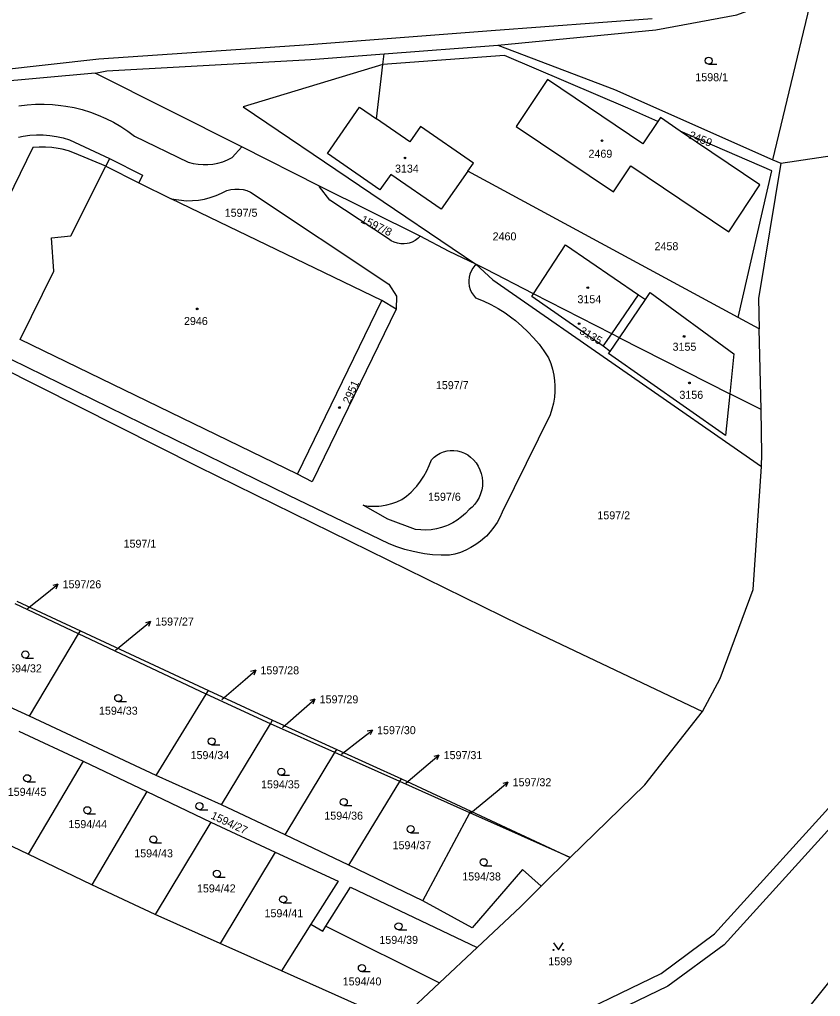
# Model space of a CAD drawing. Extents: x -679220 to -673243, y -1075091 to -1066557.
# Drawn here: x -677540.5 to -677370.2, y -1071612.6 to -1071405.1 of the extents above; entities that cross this region are included whole.
import ezdxf

# ---------------------------------------------------------------- set-up
doc = ezdxf.new("R2010")
doc.units = 0
for name, color, linetype in [('Hranice parcel', 7, 'Continuous'), ('Parcelní čísla', 7, 'Continuous'), ('Pop  PČ popisy', 7, 'Continuous'), ('Vnitřní kresba', 7, 'Continuous'), ('Značky budov', 7, 'Continuous'), ('Značky kultur', 7, 'Continuous')]:
    doc.layers.add(name, color=color, linetype=linetype)

msp = doc.modelspace()

# ---------------------------------------------------------------- linework, layer by layer
at = {"layer": 'Hranice parcel'}
for p, q in [((-677380.32, -1071434.86), (-677371.5, -1071397.98)), ((-677462.95, -1071412.35), (-677438.76, -1071410.53)), ((-677463.21, -1071414.59), (-677462.95, -1071412.35)), ((-677464.55, -1071426.16), (-677463.21, -1071414.59)), ((-677493.17, -1071432.13), (-677524.38, -1071416.45)), ((-677529.81, -1071430.6), (-677521.35, -1071434.58)), ((-677516, -1071429.8), (-677504.61, -1071435.33)), ((-677495.29, -1071434.36), (-677493.17, -1071432.13)), ((-677476.71, -1071440.48), (-677493.17, -1071432.13)), ((-677522.14, -1071436.19), (-677528.8, -1071433.41)), ((-677521.35, -1071434.58), (-677522.14, -1071436.19)), ((-677380.32, -1071434.86), (-677378.65, -1071435.6)), ((-677387.71, -1071468.34), (-677445.17, -1071437.26)), ((-677455.28, -1071451.1), (-677476.71, -1071440.48)), ((-677508.19, -1071443.16), (-677504.96, -1071443.55)), ((-677463.47, -1071464.77), (-677508.19, -1071443.16)), ((-677443.5, -1071457.04), (-677444.1, -1071457.88)), ((-677481.39, -1071501.64), (-677463.47, -1071464.77)), ((-677460.42, -1071466.58), (-677463.47, -1071464.77)), ((-677412.94, -1071472.64), (-677407.43, -1071464.52)), ((-677383.25, -1071470.75), (-677387.71, -1071468.34)), ((-677382.84, -1071487.91), (-677383.25, -1071470.75)), ((-677414.92, -1071475.56), (-677412.94, -1071472.64)), ((-677412.94, -1071472.64), (-677389.5, -1071484.56)), ((-677382.84, -1071487.91), (-677389.5, -1071484.56)), ((-677427.67, -1071489.01), (-677437.86, -1071509.71)), ((-677527.92, -1071535.57), (-677541.41, -1071529.19)), ((-677541.06, -1071528.61), (-677527.52, -1071534.91)), ((-677538.35, -1071553.02), (-677527.92, -1071535.57)), ((-677527.92, -1071535.57), (-677527.52, -1071534.91)), ((-677500.8, -1071548.41), (-677527.92, -1071535.57)), ((-677527.52, -1071534.91), (-677500.29, -1071547.58)), ((-677538.35, -1071553.02), (-677552.08, -1071546.78)), ((-677511.44, -1071565.66), (-677500.8, -1071548.41)), ((-677500.8, -1071548.41), (-677500.29, -1071547.58)), ((-677487.14, -1071554.68), (-677500.8, -1071548.41)), ((-677500.29, -1071547.58), (-677486.66, -1071553.87)), ((-677511.44, -1071565.66), (-677538.35, -1071553.02)), ((-677497.52, -1071571.92), (-677487.14, -1071554.68)), ((-677487.14, -1071554.68), (-677486.66, -1071553.87)), ((-677473.41, -1071560.79), (-677487.14, -1071554.68)), ((-677486.66, -1071553.87), (-677473.03, -1071560.16)), ((-677540.61, -1071556.25), (-677526.95, -1071562.58)), ((-677483.98, -1071578.29), (-677473.41, -1071560.79)), ((-677473.41, -1071560.79), (-677473.03, -1071560.16)), ((-677459.62, -1071566.94), (-677473.41, -1071560.79)), ((-677473.03, -1071560.16), (-677459.29, -1071566.4)), ((-677526.95, -1071562.58), (-677538.62, -1071582.4)), ((-677526.95, -1071562.58), (-677513.43, -1071569.04)), ((-677497.52, -1071571.92), (-677511.44, -1071565.66)), ((-677470.46, -1071584.7), (-677459.62, -1071566.94)), ((-677459.62, -1071566.94), (-677459.29, -1071566.4)), ((-677444.72, -1071573.58), (-677459.62, -1071566.94)), ((-677459.29, -1071566.4), (-677444.53, -1071573.23)), ((-677513.43, -1071569.04), (-677525.11, -1071588.88)), ((-677513.43, -1071569.04), (-677499.77, -1071575.57)), ((-677483.98, -1071578.29), (-677497.52, -1071571.92)), ((-677454.76, -1071592.27), (-677444.72, -1071573.58)), ((-677444.72, -1071573.58), (-677444.53, -1071573.23)), ((-677423.4, -1071583.07), (-677444.72, -1071573.58)), ((-677444.53, -1071573.23), (-677423.4, -1071583.07)), ((-677538.62, -1071582.4), (-677552.22, -1071575.88)), ((-677499.77, -1071575.57), (-677511.65, -1071595.21)), ((-677499.77, -1071575.57), (-677486.12, -1071581.93)), ((-677470.46, -1071584.7), (-677483.98, -1071578.29)), ((-677486.12, -1071581.93), (-677497.84, -1071601.35)), ((-677525.11, -1071588.88), (-677538.62, -1071582.4)), ((-677423.4, -1071583.07), (-677429.57, -1071589.2)), ((-677454.76, -1071592.27), (-677470.46, -1071584.7)), ((-677511.65, -1071595.21), (-677525.11, -1071588.88)), ((-677497.84, -1071601.35), (-677511.65, -1071595.21)), ((-677478.51, -1071597.26), (-677484.77, -1071607.17)), ((-677475.33, -1071597.66), (-677451.21, -1071609.71)), ((-677484.77, -1071607.17), (-677497.84, -1071601.35)), ((-677443.18, -1071602.2), (-677451.21, -1071609.71)), ((-677460.19, -1071618.11), (-677484.77, -1071607.17)), ((-677451.21, -1071609.71), (-677460.19, -1071618.11))]:
    msp.add_line(p, q, dxfattribs=at)
for points in [[(-677547.65, -1071874.9), (-677512.13, -1071839.9), (-677494.84, -1071813.59), (-677477.52, -1071787.54), (-677474.59, -1071780.52), (-677470.62, -1071763.59), (-677466.53, -1071728.98), (-677464.55, -1071710.33), (-677463.26, -1071667.2), (-677450.4, -1071640.86), (-677427.79, -1071619.2), (-677404.1, -1071607.74), (-677392.74, -1071599.33), (-677364.3, -1071568.01), (-677352.33, -1071547.38), (-677353.42, -1071517.27), (-677364.45, -1071472.8), (-677366.9, -1071460.72), (-677361.99, -1071451.74), (-677335.82, -1071408.46), (-677315.48, -1071374.36), (-677305.32, -1071362.98)], [(-677378.65, -1071435.6), (-677361.04, -1071432.92), (-677352.11, -1071426.05), (-677332.52, -1071385.41), (-677330.04, -1071377.21)], [(-677438.76, -1071410.53), (-677405.19, -1071407.24), (-677388.02, -1071404.05), (-677371.5, -1071397.98)], [(-677438.76, -1071410.53), (-677414.01, -1071419.93), (-677380.32, -1071434.86)], [(-677524.38, -1071416.45), (-677521.9, -1071415.96), (-677505.24, -1071415.05), (-677478.52, -1071413.52), (-677462.95, -1071412.35)], [(-677404.76, -1071426.68), (-677411.19, -1071423.9), (-677437.37, -1071412.67), (-677463.21, -1071414.59)], [(-677524.38, -1071416.45), (-677547.16, -1071418.48), (-677560.78, -1071423.33), (-677569.14, -1071429.68), (-677576.12, -1071438.38), (-677587.19, -1071457.4)], [(-677404.76, -1071426.68), (-677407.98, -1071431.47), (-677428.26, -1071417.82), (-677434.93, -1071427.78), (-677414.24, -1071441.63), (-677410.55, -1071436.11), (-677389.69, -1071450.17), (-677383.07, -1071440.18), (-677400.01, -1071428.74)], [(-677540.59, -1071423.4), (-677538.82, -1071423.17), (-677537.03, -1071423.05), (-677535.24, -1071423.02), (-677533.45, -1071423.1), (-677531.67, -1071423.28), (-677530.61, -1071423.43), (-677528.85, -1071423.76), (-677527.11, -1071424.19), (-677525.4, -1071424.72), (-677523.72, -1071425.34), (-677522.09, -1071426.06), (-677520.49, -1071426.87), (-677518.94, -1071427.76), (-677517.44, -1071428.74), (-677516, -1071429.8)], [(-677445.17, -1071437.26), (-677450.84, -1071445.35), (-677461.56, -1071437.96), (-677463.84, -1071441.24), (-677475, -1071433.51), (-677468.17, -1071423.65), (-677464.55, -1071426.16)], [(-677445.17, -1071437.26), (-677443.95, -1071435.53), (-677455.23, -1071427.81), (-677457.49, -1071431.06), (-677464.55, -1071426.16)], [(-677400.01, -1071428.74), (-677404.23, -1071425.89), (-677404.76, -1071426.68)], [(-677387.71, -1071468.34), (-677380.52, -1071437.19), (-677400.01, -1071428.74)], [(-677540.69, -1071430.01), (-677539.7, -1071429.82), (-677538.28, -1071429.63), (-677536.85, -1071429.55), (-677535.42, -1071429.56), (-677534, -1071429.67), (-677532.58, -1071429.88), (-677531.18, -1071430.19), (-677529.81, -1071430.6)], [(-677537.61, -1071432.26), (-677551.2, -1071459.97), (-677546.91, -1071462.35), (-677548.32, -1071463.81), (-677550.63, -1071464.06), (-677553.26, -1071461.57)], [(-677528.8, -1071433.41), (-677530.07, -1071432.96), (-677531.38, -1071432.61), (-677532.23, -1071432.43), (-677533.56, -1071432.24), (-677534.91, -1071432.15), (-677536.26, -1071432.15), (-677537.61, -1071432.26)], [(-677521.35, -1071434.58), (-677514.3, -1071438.12), (-677515.11, -1071439.72), (-677508.19, -1071443.16)], [(-677504.61, -1071435.33), (-677503.56, -1071435.61), (-677502.5, -1071435.79), (-677501.42, -1071435.88), (-677500.44, -1071435.86), (-677499.36, -1071435.76), (-677498.3, -1071435.55), (-677497.26, -1071435.25), (-677496.26, -1071434.85), (-677495.29, -1071434.36)], [(-677481.39, -1071501.64), (-677540.3, -1071473.02), (-677533.17, -1071458.51), (-677533.66, -1071451.42), (-677529.58, -1071450.99), (-677522.14, -1071436.19)], [(-677378.65, -1071435.6), (-677383.4, -1071464.3), (-677383.25, -1071470.75)], [(-677504.96, -1071443.55), (-677503.68, -1071443.53), (-677502.4, -1071443.41), (-677501.15, -1071443.19), (-677499.91, -1071442.88), (-677498.69, -1071442.46), (-677497.51, -1071441.96), (-677496.37, -1071441.36), (-677495.55, -1071441.16), (-677494.72, -1071441.06), (-677494.61, -1071441.06), (-677493.76, -1071441.07), (-677492.93, -1071441.18), (-677492.11, -1071441.39), (-677491.33, -1071441.7)], [(-677462.01, -1071451.65), (-677474.52, -1071443.4), (-677476.68, -1071440.62), (-677476.71, -1071440.48)], [(-677491.33, -1071441.7), (-677461.97, -1071461.27), (-677460.34, -1071463.84), (-677460.42, -1071466.58)], [(-677455.28, -1071451.1), (-677455.79, -1071451.58), (-677456.36, -1071451.99), (-677456.99, -1071452.32), (-677457.65, -1071452.55), (-677458.03, -1071452.64), (-677458.73, -1071452.71), (-677459.44, -1071452.69), (-677460.13, -1071452.57), (-677460.8, -1071452.36), (-677461.43, -1071452.05), (-677462.01, -1071451.65)], [(-677443.5, -1071457.04), (-677449.13, -1071454.3), (-677455.28, -1071451.1)], [(-677431.23, -1071463.34), (-677424.43, -1071452.89), (-677408.87, -1071463.53), (-677407.43, -1071464.52)], [(-677587.19, -1071457.4), (-677502.54, -1071500), (-677433.93, -1071533.74), (-677395.28, -1071552.08)], [(-677431.23, -1071463.34), (-677441.37, -1071458.11), (-677443.5, -1071457.04)], [(-677444.1, -1071457.88), (-677444.45, -1071458.49), (-677444.72, -1071459.14), (-677444.89, -1071459.82), (-677444.96, -1071460.52), (-677444.94, -1071461.01), (-677444.85, -1071461.71), (-677444.65, -1071462.38), (-677444.36, -1071463.02), (-677443.98, -1071463.62), (-677443.52, -1071464.15), (-677441.88, -1071464.83), (-677440.29, -1071465.59), (-677438.73, -1071466.45), (-677437.23, -1071467.39), (-677435.79, -1071468.42), (-677435.02, -1071469.02), (-677433.67, -1071470.17), (-677432.39, -1071471.39), (-677431.18, -1071472.68), (-677430.04, -1071474.04), (-677428.99, -1071475.46), (-677428.01, -1071476.94), (-677427.55, -1071478.12), (-677427.18, -1071479.34), (-677426.91, -1071480.58), (-677426.74, -1071481.84), (-677426.68, -1071482.78), (-677426.68, -1071484.05), (-677426.78, -1071485.31), (-677426.98, -1071486.57), (-677427.28, -1071487.8), (-677427.67, -1071489.01)], [(-677414.92, -1071475.56), (-677416.37, -1071474.48), (-677431.59, -1071463.89), (-677431.23, -1071463.34)], [(-677412.94, -1071472.64), (-677414.55, -1071471.82), (-677431.23, -1071463.34)], [(-677407.43, -1071464.52), (-677406.39, -1071463.01), (-677388.61, -1071476.05), (-677389.5, -1071484.56)], [(-677460.42, -1071466.58), (-677478.29, -1071503.3), (-677481.39, -1071501.64)], [(-677361.41, -1071471.95), (-677350.43, -1071516.86), (-677349.56, -1071533.03), (-677349.29, -1071547.83), (-677361.83, -1071569.86), (-677390.7, -1071601.66), (-677402.66, -1071610.43), (-677426.13, -1071621.73), (-677447.8, -1071642.64), (-677460.12, -1071667.74), (-677461.31, -1071710.35), (-677463.55, -1071729.64)], [(-677461.89, -1071516.47), (-677483.23, -1071506.15), (-677542.2, -1071477.26), (-677549.7, -1071473.72)], [(-677389.5, -1071484.56), (-677390.43, -1071493.45), (-677415.25, -1071475.99), (-677414.92, -1071475.56)], [(-677449.46, -1071732.84), (-677430.89, -1071685.08), (-677401.23, -1071649.29), (-677387.93, -1071633.95), (-677371.26, -1071613.2), (-677344.18, -1071579.41), (-677335.48, -1071540.9), (-677322.24, -1071482.13)], [(-677395.28, -1071552.08), (-677391.53, -1071545.07), (-677384.51, -1071526.16), (-677382.75, -1071500), (-677382.69, -1071497.39), (-677382.84, -1071487.91)], [(-677467.45, -1071508.25), (-677466.33, -1071508.41), (-677465.21, -1071508.47), (-677464.08, -1071508.44), (-677463.52, -1071508.38), (-677462.41, -1071508.19), (-677461.32, -1071507.9), (-677460.25, -1071507.52), (-677459.23, -1071507.05), (-677458.2, -1071506.28), (-677457.23, -1071505.43), (-677456.34, -1071504.51), (-677456.04, -1071504.17), (-677455.24, -1071503.16), (-677454.53, -1071502.09), (-677453.9, -1071500.96), (-677453.36, -1071499.8), (-677452.91, -1071498.59), (-677452.35, -1071498.05), (-677451.73, -1071497.58), (-677451.06, -1071497.2), (-677450.34, -1071496.91), (-677449.59, -1071496.71), (-677448.89, -1071496.62), (-677448.12, -1071496.61), (-677447.35, -1071496.7), (-677446.59, -1071496.89), (-677445.87, -1071497.18), (-677445.2, -1071497.55), (-677444.57, -1071498.01), (-677443.96, -1071498.59), (-677443.42, -1071499.24), (-677442.96, -1071499.95), (-677442.59, -1071500.71), (-677442.32, -1071501.51), (-677442.13, -1071502.33), (-677442.05, -1071503.17), (-677442.05, -1071503.32), (-677442.08, -1071504.16), (-677442.22, -1071505), (-677442.45, -1071505.81), (-677442.77, -1071506.58), (-677443.19, -1071507.32), (-677443.69, -1071508), (-677444.26, -1071508.62), (-677444.91, -1071509.16), (-677445.67, -1071509.98), (-677446.5, -1071510.72), (-677447.4, -1071511.39), (-677448.35, -1071511.97), (-677449.35, -1071512.47), (-677449.72, -1071512.62), (-677450.78, -1071513), (-677451.86, -1071513.27), (-677452.96, -1071513.45), (-677454.08, -1071513.53), (-677455.19, -1071513.5), (-677456.3, -1071513.38)], [(-677456.3, -1071513.38), (-677462.2, -1071511.21), (-677467.45, -1071508.25)], [(-677437.86, -1071509.71), (-677438.36, -1071510.83), (-677438.95, -1071511.9), (-677439.63, -1071512.92), (-677440.39, -1071513.88), (-677441.22, -1071514.78), (-677441.54, -1071515.08), (-677442.46, -1071515.88), (-677443.45, -1071516.6), (-677444.5, -1071517.24), (-677445.59, -1071517.79), (-677446.73, -1071518.25), (-677447.9, -1071518.61), (-677449.09, -1071518.88), (-677450.87, -1071518.87), (-677452.65, -1071518.76), (-677454.41, -1071518.54), (-677455.07, -1071518.44), (-677456.81, -1071518.09), (-677458.53, -1071517.65), (-677460.23, -1071517.1), (-677461.89, -1071516.47)], [(-677423.4, -1071583.07), (-677407.58, -1071567.63), (-677395.28, -1071552.08)], [(-677486.12, -1071581.93), (-677472.75, -1071588.09), (-677478.51, -1071597.26)], [(-677429.57, -1071589.2), (-677433.57, -1071585.62), (-677444.26, -1071598.05), (-677454.76, -1071592.27)], [(-677475.33, -1071597.66), (-677470.11, -1071589.35), (-677443.18, -1071602.2)], [(-677429.57, -1071589.2), (-677433.96, -1071593.57), (-677443.18, -1071602.2)], [(-677478.51, -1071597.26), (-677476, -1071598.72), (-677475.33, -1071597.66)]]:
    msp.add_lwpolyline(points, dxfattribs=at)
at = {"layer": 'Pop  PČ popisy'}
for p, q in [((-677534.64, -1071526.91), (-677532.31, -1071525.02)), ((-677532.31, -1071525.02), (-677533.4, -1071525.26)), ((-677532.31, -1071525.02), (-677532.77, -1071526.04)), ((-677538.73, -1071530.21), (-677534.64, -1071526.91)), ((-677514.94, -1071534.85), (-677512.61, -1071532.96)), ((-677512.61, -1071532.96), (-677513.7, -1071533.2)), ((-677512.61, -1071532.96), (-677513.07, -1071533.98)), ((-677520.03, -1071539), (-677514.94, -1071534.85)), ((-677492.52, -1071545.27), (-677490.26, -1071543.3)), ((-677490.26, -1071543.3), (-677491.34, -1071543.58)), ((-677490.26, -1071543.3), (-677490.68, -1071544.34)), ((-677497.48, -1071549.54), (-677492.52, -1071545.27)), ((-677479.93, -1071551.44), (-677477.67, -1071549.47)), ((-677477.67, -1071549.47), (-677478.75, -1071549.75)), ((-677477.67, -1071549.47), (-677478.09, -1071550.51)), ((-677484.58, -1071555.46), (-677479.93, -1071551.44)), ((-677467.82, -1071557.88), (-677465.46, -1071556.03)), ((-677465.46, -1071556.03), (-677466.55, -1071556.25)), ((-677465.46, -1071556.03), (-677465.94, -1071557.04)), ((-677472, -1071561.15), (-677467.82, -1071557.88)), ((-677453.6, -1071563.26), (-677451.3, -1071561.33)), ((-677451.3, -1071561.33), (-677452.39, -1071561.59)), ((-677451.3, -1071561.33), (-677451.75, -1071562.36)), ((-677458.35, -1071567.26), (-677453.6, -1071563.26)), ((-677438.95, -1071569), (-677436.65, -1071567.07)), ((-677436.65, -1071567.07), (-677437.74, -1071567.33)), ((-677436.65, -1071567.07), (-677437.1, -1071568.1)), ((-677444.51, -1071573.58), (-677438.95, -1071569))]:
    msp.add_line(p, q, dxfattribs=at)
at = {"layer": 'Vnitřní kresba'}
for p, q in [((-677406, -1071404.9), (-677440.22, -1071407.46)), ((-677440.22, -1071407.46), (-677478.92, -1071410.44)), ((-677478.92, -1071410.44), (-677523.61, -1071413.49)), ((-677523.61, -1071413.49), (-677548.01, -1071416.23)), ((-677463.21, -1071414.59), (-677492.92, -1071423.58)), ((-677492.92, -1071423.58), (-677443.5, -1071457.04)), ((-677522.14, -1071436.19), (-677515.11, -1071439.72)), ((-677443.5, -1071457.04), (-677439.84, -1071460.34)), ((-677439.84, -1071460.34), (-677382.75, -1071500)), ((-677414.55, -1071471.82), (-677408.87, -1071463.53)), ((-677416.37, -1071474.48), (-677414.55, -1071471.82))]:
    msp.add_line(p, q, dxfattribs=at)
at = {"layer": 'Značky budov'}
for centre in [(-677416.65, -1071430.8), (-677458.53, -1071434.46), (-677419.67, -1071462.01), (-677502.7, -1071466.53), (-677421.51, -1071469.66), (-677399.2, -1071472.38), (-677398.06, -1071482.24), (-677472.46, -1071487.48)]:
    msp.add_circle(centre, 0.175, dxfattribs=at)
at = {"layer": 'Značky kultur'}
for p, q in [((-677393.99, -1071414.54), (-677392.24, -1071414.54)), ((-677539.22, -1071540.7), (-677537.47, -1071540.7)), ((-677519.48, -1071549.97), (-677517.73, -1071549.97)), ((-677499.63, -1071559.15), (-677497.88, -1071559.15)), ((-677484.82, -1071565.62), (-677483.07, -1071565.62)), ((-677538.83, -1071566.99), (-677537.08, -1071566.99)), ((-677526.05, -1071573.79), (-677524.3, -1071573.79)), ((-677502.21, -1071572.92), (-677500.46, -1071572.92)), ((-677471.54, -1071572.05), (-677469.79, -1071572.05)), ((-677457.33, -1071577.81), (-677455.58, -1071577.81)), ((-677512, -1071579.99), (-677510.25, -1071579.99)), ((-677441.81, -1071584.84), (-677440.06, -1071584.84)), ((-677498.51, -1071587.29), (-677496.76, -1071587.29)), ((-677484.42, -1071592.73), (-677482.67, -1071592.73)), ((-677459.9, -1071598.44), (-677458.15, -1071598.44)), ((-677467.69, -1071607.33), (-677465.94, -1071607.33))]:
    msp.add_line(p, q, dxfattribs=at)
msp.add_lwpolyline([(-677426.93, -1071601.21), (-677425.93, -1071602.71), (-677424.93, -1071601.21)], dxfattribs=at)
for centre, radius in [((-677393.99, -1071413.79), 0.75), ((-677539.22, -1071539.95), 0.75), ((-677519.48, -1071549.22), 0.75), ((-677499.63, -1071558.4), 0.75), ((-677538.83, -1071566.24), 0.75), ((-677484.82, -1071564.87), 0.75), ((-677502.21, -1071572.17), 0.75), ((-677471.54, -1071571.3), 0.75), ((-677526.05, -1071573.04), 0.75), ((-677457.33, -1071577.06), 0.75), ((-677512, -1071579.24), 0.75), ((-677441.81, -1071584.09), 0.75), ((-677498.51, -1071586.54), 0.75), ((-677484.42, -1071591.98), 0.75), ((-677459.9, -1071597.69), 0.75), ((-677426.93, -1071602.71), 0.1), ((-677424.93, -1071602.71), 0.1), ((-677467.69, -1071606.58), 0.75)]:
    msp.add_circle(centre, radius, dxfattribs=at)

# ---------------------------------------------------------------- texts
at = {"layer": 'Parcelní čísla'}
for s, p in [('1598/1', (-677396.81, -1071418.15)), ('2469', (-677419.52, -1071434.41)), ('3134', (-677460.65, -1071437.57)), ('1597/5', (-677496.84, -1071446.95)), ('2460', (-677439.9, -1071451.97)), ('2458', (-677405.48, -1071454.06)), ('3154', (-677421.87, -1071465.32)), ('2946', (-677505.5, -1071469.95)), ('3155', (-677401.65, -1071475.42)), ('1597/7', (-677451.96, -1071483.58)), ('3156', (-677400.2, -1071485.63)), ('1597/6', (-677453.62, -1071507.29)), ('1597/2', (-677417.63, -1071511.23)), ('1597/1', (-677518.34, -1071517.26)), ('1597/26', (-677531.31, -1071525.88)), ('1597/27', (-677511.62, -1071533.8)), ('1594/32', (-677543.93, -1071543.75)), ('1597/28', (-677489.25, -1071544.16)), ('1597/29', (-677476.66, -1071550.33)), ('1594/33', (-677523.56, -1071552.74)), ('1597/30', (-677464.46, -1071556.88)), ('1594/34', (-677504.1, -1071562.18)), ('1597/31', (-677450.31, -1071562.18)), ('1594/35', (-677489.12, -1071568.39)), ('1597/32', (-677435.64, -1071567.94)), ('1594/45', (-677542.96, -1071569.98)), ('1594/36', (-677475.67, -1071575.04)), ('1594/44', (-677530.06, -1071576.84)), ('1594/37', (-677461.17, -1071581.32)), ('1594/43', (-677516.07, -1071583.04)), ('1594/38', (-677446.36, -1071587.96)), ('1594/42', (-677502.74, -1071590.5)), ('1594/41', (-677488.38, -1071595.77)), ('1594/39', (-677463.97, -1071601.43)), ('1599', (-677428.06, -1071605.99)), ('1594/40', (-677471.76, -1071610.26))]:
    msp.add_text(s, height=1.7, dxfattribs=at).set_placement(p)
for s, rotation, p in [('2459', 338, (-677398.36, -1071430.24)), ('1597/8', 334, (-677468.07, -1071448.1)), ('3135', 330, (-677421.6, -1071471.67)), ('2951', 66, (-677470.28, -1071486.83)), ('1594/27', 335, (-677499.94, -1071574.74))]:
    msp.add_text(s, height=1.7, rotation=rotation, dxfattribs=at).set_placement(p)

doc.saveas('drawing.dxf')
